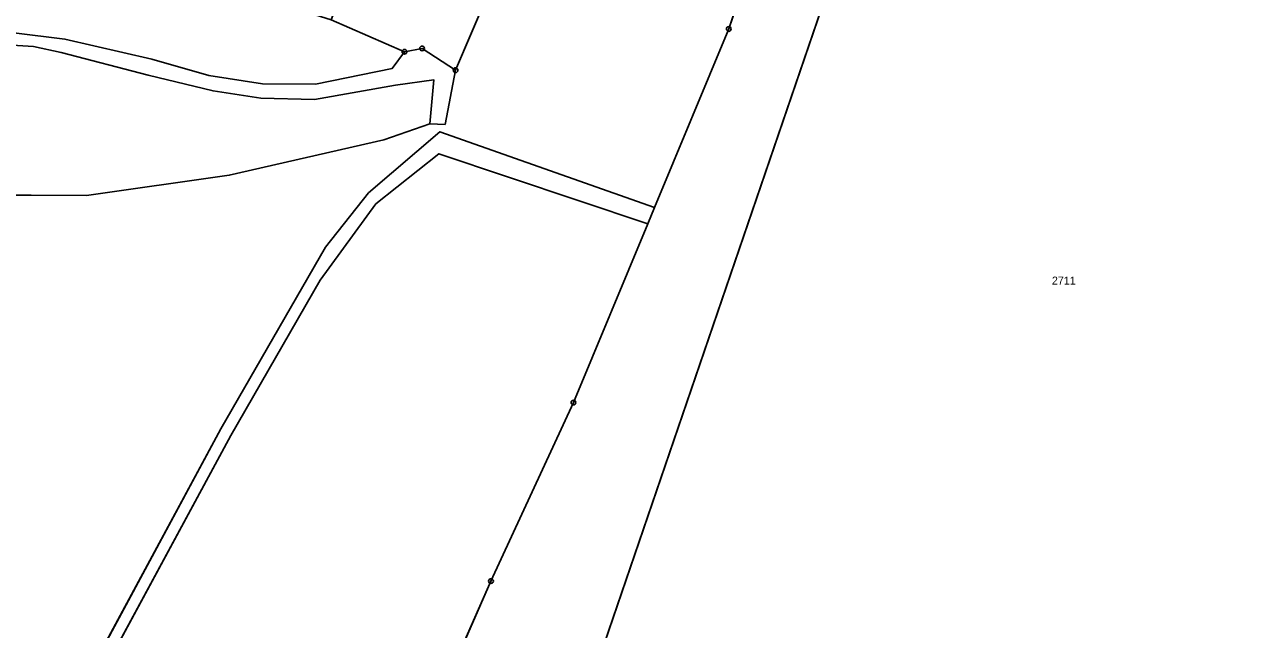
# Model space of a CAD drawing. Extents: x -689422 to -685210, y -987725 to -982160.
# Drawn here: x -688252 to -687992.2, y -985985 to -985856.6 of the extents above; entities that cross this region are included whole.
import ezdxf

# ---------------------------------------------------------------- set-up
doc = ezdxf.new("R2010")
doc.units = 0
for name, color, linetype in [('KN_Hranice_parcel', 7, 'Continuous'), ('KN_Parcelni cisla', 7, 'Continuous'), ('KN_Polygon parcely', 7, 'Continuous'), ('KN_POZEMKY_LESNI POZEMEK', 7, 'Continuous'), ('KN_POZEMKY_ORNA PUDA', 7, 'Continuous'), ('KN_POZEMKY_OSTATNI PLOCHA', 7, 'Continuous'), ('KN_VYUZITI_17_ostatni plocha_ostatni komunikace', 7, 'Continuous'), ('KN_VYUZITI_23_ostatni plocha_manipulacni plocha', 7, 'Continuous'), ('KN_Značky bodu BP', 7, 'Continuous')]:
    doc.layers.add(name, color=color, linetype=linetype)

msp = doc.modelspace()

# ---------------------------------------------------------------- linework, layer by layer
at = {"layer": 'KN_Hranice_parcel'}
for p, q in [((-688102.38, -985857.56), (-688060.69, -985733.68)), ((-688043.61, -985739.06), (-688209.33, -986223.03)), ((-688171.29, -985862.4), (-688186.82, -985855.65)), ((-688118.15, -985895.43), (-688102.38, -985857.56)), ((-688175.67, -985881.09), (-688165.89, -985877.72)), ((-688119.59, -985898.89), (-688118.15, -985895.43)), ((-688135.4, -985936.83), (-688119.59, -985898.89))]:
    msp.add_line(p, q, dxfattribs=at)
for points in [[(-688144.59, -985825.41), (-688152.18, -985846.94), (-688160.43, -985866.3)], [(-688312.6, -985873.43), (-688294.01, -985866.34), (-688280.32, -985860.91), (-688270.9, -985858.45), (-688265.06, -985857.88), (-688254.23, -985858.36), (-688243.42, -985859.69), (-688224.92, -985863.94), (-688212.81, -985867.46), (-688201.45, -985869.18), (-688190.15, -985869.26), (-688173.88, -985865.93), (-688171.29, -985862.4)], [(-688312, -985875.72), (-688292.95, -985868.69), (-688279.4, -985863.55), (-688270.63, -985861.01), (-688265.13, -985860.73), (-688254.58, -985861.01), (-688250.06, -985861.28), (-688244.23, -985862.53), (-688225.73, -985867.33), (-688211.93, -985870.7), (-688201.77, -985872.25), (-688190.4, -985872.52), (-688173.15, -985869.46)], [(-688160.43, -985866.3), (-688167.53, -985861.7), (-688171.29, -985862.4)], [(-688165.89, -985877.72), (-688162.66, -985877.82), (-688160.43, -985866.3)], [(-688173.15, -985869.46), (-688165.05, -985868.34), (-688165.89, -985877.72)], [(-688298.64, -986120.9), (-688266.76, -986055.76), (-688239.95, -985997.4), (-688210.28, -985942.44), (-688188.03, -985903.85), (-688178.9, -985892.32), (-688163.74, -985879.37), (-688118.15, -985895.43)], [(-688354.12, -986078.58), (-688330.93, -986034.27), (-688325.79, -986018.8), (-688308.39, -985977.94), (-688295.39, -985952.48), (-688273.95, -985914.39), (-688262.37, -985892.79), (-688238.83, -985892.9), (-688208.5, -985888.6), (-688175.67, -985881.09)], [(-688119.59, -985898.89), (-688163.97, -985884.03), (-688177.33, -985894.65), (-688189.2, -985910.89), (-688208.17, -985943.8), (-688238.28, -985999.52), (-688262.24, -986051.83), (-688294.76, -986121.97)], [(-688251.46, -986217.87), (-688246.23, -986195.81), (-688210.04, -986104.42), (-688152.9, -985974.73), (-688135.4, -985936.83)]]:
    msp.add_lwpolyline(points, dxfattribs=at)
at = {"layer": 'KN_Polygon parcely'}
for points in [[(-688239.95, -985997.4), (-688210.28, -985942.44), (-688188.03, -985903.85), (-688178.9, -985892.32), (-688163.74, -985879.37), (-688118.15, -985895.43), (-688102.38, -985857.56), (-688060.69, -985733.68), (-688098.59, -985721.04), (-688113.14, -985752.04), (-688126.89, -985782.42), (-688144.59, -985825.41), (-688152.18, -985846.94), (-688160.43, -985866.3), (-688162.66, -985877.82), (-688165.89, -985877.72), (-688175.67, -985881.09), (-688208.5, -985888.6), (-688238.83, -985892.9), (-688262.37, -985892.79), (-688273.95, -985914.39), (-688295.39, -985952.48), (-688308.39, -985977.94), (-688325.79, -986018.8)], [(-687977.17, -986084.07), (-687905.28, -985782.43), (-687929.48, -985774.84), (-688043.61, -985739.06), (-688209.33, -986223.03)], [(-688254.58, -985861.01), (-688250.06, -985861.28), (-688244.23, -985862.53), (-688225.73, -985867.33), (-688211.93, -985870.7), (-688201.77, -985872.25), (-688190.4, -985872.52), (-688173.15, -985869.46), (-688165.05, -985868.34), (-688165.89, -985877.72), (-688162.66, -985877.82), (-688160.43, -985866.3), (-688167.53, -985861.7), (-688171.29, -985862.4), (-688173.88, -985865.93), (-688190.15, -985869.26), (-688201.45, -985869.18), (-688212.81, -985867.46), (-688224.92, -985863.94), (-688243.42, -985859.69), (-688254.23, -985858.36)], [(-688262.37, -985892.79), (-688238.83, -985892.9), (-688208.5, -985888.6), (-688175.67, -985881.09), (-688165.89, -985877.72), (-688165.05, -985868.34), (-688173.15, -985869.46), (-688190.4, -985872.52), (-688201.77, -985872.25), (-688211.93, -985870.7), (-688225.73, -985867.33), (-688244.23, -985862.53), (-688250.06, -985861.28), (-688254.58, -985861.01)], [(-688238.28, -985999.52), (-688208.17, -985943.8), (-688189.2, -985910.89), (-688177.33, -985894.65), (-688163.97, -985884.03), (-688119.59, -985898.89), (-688118.15, -985895.43), (-688163.74, -985879.37), (-688178.9, -985892.32), (-688188.03, -985903.85), (-688210.28, -985942.44), (-688239.95, -985997.4)]]:
    msp.add_lwpolyline(points, dxfattribs=at)
for points in [[(-688043.61, -985739.06), (-688060.69, -985733.68), (-688102.38, -985857.56), (-688118.15, -985895.43), (-688119.59, -985898.89), (-688135.4, -985936.83), (-688152.9, -985974.73), (-688210.04, -986104.42), (-688246.23, -986195.81), (-688251.46, -986217.87), (-688209.33, -986223.03)], [(-688186.82, -985855.65), (-688171.29, -985862.4), (-688167.53, -985861.7), (-688160.43, -985866.3), (-688152.18, -985846.94), (-688144.59, -985825.41), (-688154.74, -985818.31), (-688169.89, -985810.95)], [(-688300.15, -985840.51), (-688321.46, -985877.52), (-688312.6, -985873.43), (-688294.01, -985866.34), (-688280.32, -985860.91), (-688270.9, -985858.45), (-688265.06, -985857.88), (-688254.23, -985858.36), (-688243.42, -985859.69), (-688224.92, -985863.94), (-688212.81, -985867.46), (-688201.45, -985869.18), (-688190.15, -985869.26), (-688173.88, -985865.93), (-688171.29, -985862.4), (-688186.82, -985855.65), (-688190.24, -985854.54), (-688215.63, -985836.69), (-688224.07, -985826.56), (-688226.51, -985824.83), (-688227.12, -985826.36), (-688287.53, -985836.47)], [(-688262.24, -986051.83), (-688294.76, -986121.97), (-688313.57, -986179.87), (-688312.67, -986194.21), (-688279.44, -986209.56), (-688251.46, -986217.87), (-688246.23, -986195.81), (-688210.04, -986104.42), (-688152.9, -985974.73), (-688135.4, -985936.83), (-688119.59, -985898.89), (-688163.97, -985884.03), (-688177.33, -985894.65), (-688189.2, -985910.89), (-688208.17, -985943.8), (-688238.28, -985999.52)]]:
    msp.add_lwpolyline(points, close=True, dxfattribs=at)
at = {"layer": 'KN_POZEMKY_LESNI POZEMEK'}
for p, q in [((-688152.18, -985846.94), (-688160.43, -985866.3)), ((-688186.82, -985855.65), (-688171.29, -985862.4)), ((-688171.29, -985862.4), (-688186.82, -985855.65)), ((-688243.42, -985859.69), (-688254.23, -985858.36)), ((-688254.58, -985861.01), (-688250.06, -985861.28)), ((-688250.06, -985861.28), (-688244.23, -985862.53)), ((-688224.92, -985863.94), (-688243.42, -985859.69)), ((-688244.23, -985862.53), (-688225.73, -985867.33)), ((-688212.81, -985867.46), (-688224.92, -985863.94)), ((-688171.29, -985862.4), (-688173.88, -985865.93)), ((-688167.53, -985861.7), (-688171.29, -985862.4)), ((-688160.43, -985866.3), (-688167.53, -985861.7)), ((-688173.88, -985865.93), (-688190.15, -985869.26)), ((-688225.73, -985867.33), (-688211.93, -985870.7)), ((-688201.45, -985869.18), (-688212.81, -985867.46)), ((-688173.15, -985869.46), (-688165.05, -985868.34)), ((-688165.05, -985868.34), (-688165.89, -985877.72)), ((-688211.93, -985870.7), (-688201.77, -985872.25)), ((-688190.15, -985869.26), (-688201.45, -985869.18)), ((-688190.4, -985872.52), (-688173.15, -985869.46)), ((-688201.77, -985872.25), (-688190.4, -985872.52)), ((-688165.89, -985877.72), (-688175.67, -985881.09)), ((-688175.67, -985881.09), (-688208.5, -985888.6)), ((-688208.5, -985888.6), (-688238.83, -985892.9)), ((-688238.83, -985892.9), (-688262.37, -985892.79))]:
    msp.add_line(p, q, dxfattribs=at)
at = {"layer": 'KN_POZEMKY_ORNA PUDA'}
for p, q in [((-688102.38, -985857.56), (-688060.69, -985733.68)), ((-688060.69, -985733.68), (-688102.38, -985857.56)), ((-688043.61, -985739.06), (-688209.33, -986223.03)), ((-688160.43, -985866.3), (-688152.18, -985846.94)), ((-688118.15, -985895.43), (-688102.38, -985857.56)), ((-688102.38, -985857.56), (-688118.15, -985895.43)), ((-688162.66, -985877.82), (-688160.43, -985866.3)), ((-688178.9, -985892.32), (-688163.74, -985879.37)), ((-688163.74, -985879.37), (-688178.9, -985892.32)), ((-688175.67, -985881.09), (-688165.89, -985877.72)), ((-688165.89, -985877.72), (-688162.66, -985877.82)), ((-688163.74, -985879.37), (-688118.15, -985895.43)), ((-688118.15, -985895.43), (-688163.74, -985879.37)), ((-688208.5, -985888.6), (-688175.67, -985881.09)), ((-688163.97, -985884.03), (-688177.33, -985894.65)), ((-688177.33, -985894.65), (-688163.97, -985884.03)), ((-688119.59, -985898.89), (-688163.97, -985884.03)), ((-688163.97, -985884.03), (-688119.59, -985898.89)), ((-688238.83, -985892.9), (-688208.5, -985888.6)), ((-688188.03, -985903.85), (-688178.9, -985892.32)), ((-688178.9, -985892.32), (-688188.03, -985903.85)), ((-688262.37, -985892.79), (-688238.83, -985892.9)), ((-688177.33, -985894.65), (-688189.2, -985910.89)), ((-688189.2, -985910.89), (-688177.33, -985894.65)), ((-688118.15, -985895.43), (-688119.59, -985898.89)), ((-688119.59, -985898.89), (-688118.15, -985895.43)), ((-688135.4, -985936.83), (-688119.59, -985898.89)), ((-688119.59, -985898.89), (-688135.4, -985936.83)), ((-688210.28, -985942.44), (-688188.03, -985903.85)), ((-688188.03, -985903.85), (-688210.28, -985942.44)), ((-688189.2, -985910.89), (-688208.17, -985943.8)), ((-688208.17, -985943.8), (-688189.2, -985910.89)), ((-688152.9, -985974.73), (-688135.4, -985936.83)), ((-688135.4, -985936.83), (-688152.9, -985974.73)), ((-688239.95, -985997.4), (-688210.28, -985942.44)), ((-688210.28, -985942.44), (-688239.95, -985997.4)), ((-688208.17, -985943.8), (-688238.28, -985999.52)), ((-688238.28, -985999.52), (-688208.17, -985943.8)), ((-688210.04, -986104.42), (-688152.9, -985974.73)), ((-688152.9, -985974.73), (-688210.04, -986104.42))]:
    msp.add_line(p, q, dxfattribs=at)
at = {"layer": 'KN_POZEMKY_OSTATNI PLOCHA'}
for p, q in [((-688209.33, -986223.03), (-688043.61, -985739.06)), ((-688254.23, -985858.36), (-688243.42, -985859.69)), ((-688250.06, -985861.28), (-688254.58, -985861.01)), ((-688244.23, -985862.53), (-688250.06, -985861.28)), ((-688243.42, -985859.69), (-688224.92, -985863.94)), ((-688225.73, -985867.33), (-688244.23, -985862.53)), ((-688224.92, -985863.94), (-688212.81, -985867.46)), ((-688173.88, -985865.93), (-688171.29, -985862.4)), ((-688171.29, -985862.4), (-688167.53, -985861.7)), ((-688167.53, -985861.7), (-688160.43, -985866.3)), ((-688190.15, -985869.26), (-688173.88, -985865.93)), ((-688160.43, -985866.3), (-688162.66, -985877.82)), ((-688211.93, -985870.7), (-688225.73, -985867.33)), ((-688212.81, -985867.46), (-688201.45, -985869.18)), ((-688165.05, -985868.34), (-688173.15, -985869.46)), ((-688165.89, -985877.72), (-688165.05, -985868.34)), ((-688201.77, -985872.25), (-688211.93, -985870.7)), ((-688201.45, -985869.18), (-688190.15, -985869.26)), ((-688173.15, -985869.46), (-688190.4, -985872.52)), ((-688190.4, -985872.52), (-688201.77, -985872.25)), ((-688162.66, -985877.82), (-688165.89, -985877.72))]:
    msp.add_line(p, q, dxfattribs=at)
at = {"layer": 'KN_VYUZITI_17_ostatni plocha_ostatni komunikace'}
for p, q in [((-688254.23, -985858.36), (-688243.42, -985859.69)), ((-688250.06, -985861.28), (-688254.58, -985861.01)), ((-688244.23, -985862.53), (-688250.06, -985861.28)), ((-688243.42, -985859.69), (-688224.92, -985863.94)), ((-688225.73, -985867.33), (-688244.23, -985862.53)), ((-688224.92, -985863.94), (-688212.81, -985867.46)), ((-688173.88, -985865.93), (-688171.29, -985862.4)), ((-688171.29, -985862.4), (-688167.53, -985861.7)), ((-688167.53, -985861.7), (-688160.43, -985866.3)), ((-688190.15, -985869.26), (-688173.88, -985865.93)), ((-688160.43, -985866.3), (-688162.66, -985877.82)), ((-688211.93, -985870.7), (-688225.73, -985867.33)), ((-688212.81, -985867.46), (-688201.45, -985869.18)), ((-688165.05, -985868.34), (-688173.15, -985869.46)), ((-688165.89, -985877.72), (-688165.05, -985868.34)), ((-688201.77, -985872.25), (-688211.93, -985870.7)), ((-688201.45, -985869.18), (-688190.15, -985869.26)), ((-688173.15, -985869.46), (-688190.4, -985872.52)), ((-688190.4, -985872.52), (-688201.77, -985872.25)), ((-688162.66, -985877.82), (-688165.89, -985877.72))]:
    msp.add_line(p, q, dxfattribs=at)
at = {"layer": 'KN_VYUZITI_23_ostatni plocha_manipulacni plocha'}
msp.add_line((-688209.33, -986223.03), (-688043.61, -985739.06), dxfattribs=at)
at = {"layer": 'KN_Značky bodu BP'}
for centre, radius in [((-688102.38, -985857.56), 0.5), ((-688102.38, -985857.56), 0.0303), ((-688167.53, -985861.7), 0.5), ((-688171.29, -985862.4), 0.5), ((-688171.29, -985862.4), 0.0303), ((-688167.53, -985861.7), 0.0303), ((-688160.43, -985866.3), 0.5), ((-688160.43, -985866.3), 0.0303), ((-688135.4, -985936.83), 0.5), ((-688135.4, -985936.83), 0.0303), ((-688152.9, -985974.73), 0.5), ((-688152.9, -985974.73), 0.0303)]:
    msp.add_circle(centre, radius, dxfattribs=at)

# ---------------------------------------------------------------- texts
at = {"layer": 'KN_Parcelni cisla'}
msp.add_text('2711', height=1.7, dxfattribs=at).set_placement((-688033.75, -985911.81))

doc.saveas('drawing.dxf')
